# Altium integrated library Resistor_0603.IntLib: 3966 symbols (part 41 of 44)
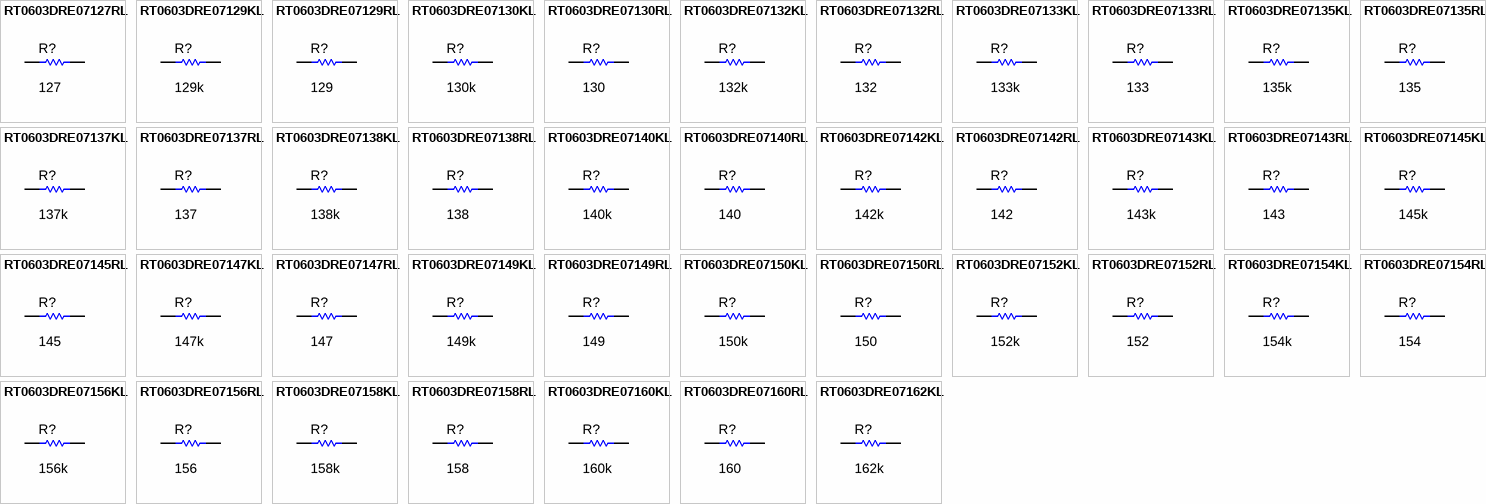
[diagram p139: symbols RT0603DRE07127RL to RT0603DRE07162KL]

## RT0603DRE07138KL
designator R?  ValueDisplayed: 138k  (hidden comment: RT0603DRE07138KL)
RES, 138 k, 0.5%, 0.1 W, 0603; Manufacturer: Yageo America; CompType: Resistor; Value: 138k; Res_ohm: 138000; Tolerance_%: 0.5; Power_W: 0.1; Value2: 0.1W; VDC_V: 75; TempCo: 50 ppm/C; SizeArea_mm2: 1.28; SizeX_mm: 1.6; SizeY_mm: 0.8; SizeZ_mm: 1; EIA_Code: E192; U/M: EA; AEC Category: Q200
signal-integrity model Resistor
simulation model Resistor
footprint 0603
footprint 0603M
footprint 0603L
footprint 0603_HV
footprint 0603S
pins: 1, 2

## RT0603DRE07138RL
designator R?  ValueDisplayed: 138  (hidden comment: RT0603DRE07138RL)
RES, 138, 0.5%, 0.1 W, 0603; Manufacturer: Yageo America; CompType: Resistor; Value: 138; Value_Code: 138R; Tolerance_%: 0.5; Power_W: 0.1; Value2: 0.1W; VDC_V: 75; TempCo: 50 ppm/C; SizeArea_mm2: 1.28; SizeX_mm: 1.6; SizeY_mm: 0.8; SizeZ_mm: 1; EIA_Code: E192; U/M: EA; AEC Category: Q200
signal-integrity model Resistor
simulation model Resistor
footprint 0603
footprint 0603M
footprint 0603L
footprint 0603_HV
footprint 0603S
pins: 1, 2

## RT0603DRE07140KL
designator R?  ValueDisplayed: 140k  (hidden comment: RT0603DRE07140KL)
RES, 140 k, 0.5%, 0.1 W, 0603; Manufacturer: Yageo America; CompType: Resistor; Value: 140k; Res_ohm: 140000; Tolerance_%: 0.5; Power_W: 0.1; Value2: 0.1W; VDC_V: 75; TempCo: 50 ppm/C; SizeArea_mm2: 1.28; SizeX_mm: 1.6; SizeY_mm: 0.8; SizeZ_mm: 1; EIA_Code: E192; U/M: EA; AEC Category: Q200
signal-integrity model Resistor
simulation model Resistor
footprint 0603
footprint 0603M
footprint 0603L
footprint 0603_HV
footprint 0603S
pins: 1, 2

## RT0603DRE07140RL
designator R?  ValueDisplayed: 140  (hidden comment: RT0603DRE07140RL)
RES, 140, 0.5%, 0.1 W, 0603; Manufacturer: Yageo America; CompType: Resistor; Value: 140; Value_Code: 140R; Tolerance_%: 0.5; Power_W: 0.1; Value2: 0.1W; VDC_V: 75; TempCo: 50 ppm/C; SizeArea_mm2: 1.28; SizeX_mm: 1.6; SizeY_mm: 0.8; SizeZ_mm: 1; EIA_Code: E192; U/M: EA; AEC Category: Q200
signal-integrity model Resistor
simulation model Resistor
footprint 0603
footprint 0603M
footprint 0603L
footprint 0603_HV
footprint 0603S
pins: 1, 2

## RT0603DRE07142KL
designator R?  ValueDisplayed: 142k  (hidden comment: RT0603DRE07142KL)
RES, 142 k, 0.5%, 0.1 W, 0603; Manufacturer: Yageo America; CompType: Resistor; Value: 142k; Res_ohm: 142000; Tolerance_%: 0.5; Power_W: 0.1; Value2: 0.1W; VDC_V: 75; TempCo: 50 ppm/C; SizeArea_mm2: 1.28; SizeX_mm: 1.6; SizeY_mm: 0.8; SizeZ_mm: 1; EIA_Code: E192; U/M: EA; AEC Category: Q200
signal-integrity model Resistor
simulation model Resistor
footprint 0603
footprint 0603M
footprint 0603L
footprint 0603_HV
footprint 0603S
pins: 1, 2

## RT0603DRE07142RL
designator R?  ValueDisplayed: 142  (hidden comment: RT0603DRE07142RL)
RES, 142, 0.5%, 0.1 W, 0603; Manufacturer: Yageo America; CompType: Resistor; Value: 142; Value_Code: 142R; Tolerance_%: 0.5; Power_W: 0.1; Value2: 0.1W; VDC_V: 75; TempCo: 50 ppm/C; SizeArea_mm2: 1.28; SizeX_mm: 1.6; SizeY_mm: 0.8; SizeZ_mm: 1; EIA_Code: E192; U/M: EA; AEC Category: Q200
signal-integrity model Resistor
simulation model Resistor
footprint 0603
footprint 0603M
footprint 0603L
footprint 0603_HV
footprint 0603S
pins: 1, 2

## RT0603DRE07143KL
designator R?  ValueDisplayed: 143k  (hidden comment: RT0603DRE07143KL)
RES, 143 k, 0.5%, 0.1 W, 0603; Manufacturer: Yageo America; CompType: Resistor; Value: 143k; Res_ohm: 143000; Tolerance_%: 0.5; Power_W: 0.1; Value2: 0.1W; VDC_V: 75; TempCo: 50 ppm/C; SizeArea_mm2: 1.28; SizeX_mm: 1.6; SizeY_mm: 0.8; SizeZ_mm: 1; EIA_Code: E192; U/M: EA; AEC Category: Q200
signal-integrity model Resistor
simulation model Resistor
footprint 0603
footprint 0603M
footprint 0603L
footprint 0603_HV
footprint 0603S
pins: 1, 2

## RT0603DRE07143RL
designator R?  ValueDisplayed: 143  (hidden comment: RT0603DRE07143RL)
RES, 143, 0.5%, 0.1 W, 0603; Manufacturer: Yageo America; CompType: Resistor; Value: 143; Value_Code: 143R; Tolerance_%: 0.5; Power_W: 0.1; Value2: 0.1W; VDC_V: 75; TempCo: 50 ppm/C; SizeArea_mm2: 1.28; SizeX_mm: 1.6; SizeY_mm: 0.8; SizeZ_mm: 1; EIA_Code: E192; U/M: EA; AEC Category: Q200
signal-integrity model Resistor
simulation model Resistor
footprint 0603
footprint 0603M
footprint 0603L
footprint 0603_HV
footprint 0603S
pins: 1, 2

## RT0603DRE07145KL
designator R?  ValueDisplayed: 145k  (hidden comment: RT0603DRE07145KL)
RES, 145 k, 0.5%, 0.1 W, 0603; Manufacturer: Yageo America; CompType: Resistor; Value: 145k; Res_ohm: 145000; Tolerance_%: 0.5; Power_W: 0.1; Value2: 0.1W; VDC_V: 75; TempCo: 50 ppm/C; SizeArea_mm2: 1.28; SizeX_mm: 1.6; SizeY_mm: 0.8; SizeZ_mm: 1; EIA_Code: E192; U/M: EA; AEC Category: Q200
signal-integrity model Resistor
simulation model Resistor
footprint 0603
footprint 0603M
footprint 0603L
footprint 0603_HV
footprint 0603S
pins: 1, 2

## RT0603DRE07145RL
designator R?  ValueDisplayed: 145  (hidden comment: RT0603DRE07145RL)
RES, 145, 0.5%, 0.1 W, 0603; Manufacturer: Yageo America; CompType: Resistor; Value: 145; Value_Code: 145R; Tolerance_%: 0.5; Power_W: 0.1; Value2: 0.1W; VDC_V: 75; TempCo: 50 ppm/C; SizeArea_mm2: 1.28; SizeX_mm: 1.6; SizeY_mm: 0.8; SizeZ_mm: 1; EIA_Code: E192; U/M: EA; AEC Category: Q200
signal-integrity model Resistor
simulation model Resistor
footprint 0603
footprint 0603M
footprint 0603L
footprint 0603_HV
footprint 0603S
pins: 1, 2

## RT0603DRE07147KL
designator R?  ValueDisplayed: 147k  (hidden comment: RT0603DRE07147KL)
RES, 147 k, 0.5%, 0.1 W, 0603; Manufacturer: Yageo America; CompType: Resistor; Value: 147k; Res_ohm: 147000; Tolerance_%: 0.5; Power_W: 0.1; Value2: 0.1W; VDC_V: 75; TempCo: 50 ppm/C; SizeArea_mm2: 1.28; SizeX_mm: 1.6; SizeY_mm: 0.8; SizeZ_mm: 1; EIA_Code: E192; U/M: EA; AEC Category: Q200
signal-integrity model Resistor
simulation model Resistor
footprint 0603
footprint 0603M
footprint 0603L
footprint 0603_HV
footprint 0603S
pins: 1, 2

## RT0603DRE07147RL
designator R?  ValueDisplayed: 147  (hidden comment: RT0603DRE07147RL)
RES, 147, 0.5%, 0.1 W, 0603; Manufacturer: Yageo America; CompType: Resistor; Value: 147; Value_Code: 147R; Tolerance_%: 0.5; Power_W: 0.1; Value2: 0.1W; VDC_V: 75; TempCo: 50 ppm/C; SizeArea_mm2: 1.28; SizeX_mm: 1.6; SizeY_mm: 0.8; SizeZ_mm: 1; EIA_Code: E192; U/M: EA; AEC Category: Q200
signal-integrity model Resistor
simulation model Resistor
footprint 0603
footprint 0603M
footprint 0603L
footprint 0603_HV
footprint 0603S
pins: 1, 2

## RT0603DRE07149KL
designator R?  ValueDisplayed: 149k  (hidden comment: RT0603DRE07149KL)
RES, 149 k, 0.5%, 0.1 W, 0603; Manufacturer: Yageo America; CompType: Resistor; Value: 149k; Res_ohm: 149000; Tolerance_%: 0.5; Power_W: 0.1; Value2: 0.1W; VDC_V: 75; TempCo: 50 ppm/C; SizeArea_mm2: 1.28; SizeX_mm: 1.6; SizeY_mm: 0.8; SizeZ_mm: 1; EIA_Code: E192; U/M: EA; AEC Category: Q200
signal-integrity model Resistor
simulation model Resistor
footprint 0603
footprint 0603M
footprint 0603L
footprint 0603_HV
footprint 0603S
pins: 1, 2

## RT0603DRE07149RL
designator R?  ValueDisplayed: 149  (hidden comment: RT0603DRE07149RL)
RES, 149, 0.5%, 0.1 W, 0603; Manufacturer: Yageo America; CompType: Resistor; Value: 149; Value_Code: 149R; Tolerance_%: 0.5; Power_W: 0.1; Value2: 0.1W; VDC_V: 75; TempCo: 50 ppm/C; SizeArea_mm2: 1.28; SizeX_mm: 1.6; SizeY_mm: 0.8; SizeZ_mm: 1; EIA_Code: E192; U/M: EA; AEC Category: Q200
signal-integrity model Resistor
simulation model Resistor
footprint 0603
footprint 0603M
footprint 0603L
footprint 0603_HV
footprint 0603S
pins: 1, 2

## RT0603DRE07150KL
designator R?  ValueDisplayed: 150k  (hidden comment: RT0603DRE07150KL)
RES, 150 k, 0.5%, 0.1 W, 0603; Manufacturer: Yageo America; CompType: Resistor; Value: 150k; Res_ohm: 150000; Tolerance_%: 0.5; Power_W: 0.1; Value2: 0.1W; VDC_V: 75; TempCo: 50 ppm/C; SizeArea_mm2: 1.28; SizeX_mm: 1.6; SizeY_mm: 0.8; SizeZ_mm: 1; EIA_Code: E192; U/M: EA; AEC Category: Q200
signal-integrity model Resistor
simulation model Resistor
footprint 0603
footprint 0603M
footprint 0603L
footprint 0603_HV
footprint 0603S
pins: 1, 2

## RT0603DRE07150RL
designator R?  ValueDisplayed: 150  (hidden comment: RT0603DRE07150RL)
RES, 150, 0.5%, 0.1 W, 0603; Manufacturer: Yageo America; CompType: Resistor; Value: 150; Value_Code: 150R; Tolerance_%: 0.5; Power_W: 0.1; Value2: 0.1W; VDC_V: 75; TempCo: 50 ppm/C; SizeArea_mm2: 1.28; SizeX_mm: 1.6; SizeY_mm: 0.8; SizeZ_mm: 1; EIA_Code: E192; U/M: EA; AEC Category: Q200
signal-integrity model Resistor
simulation model Resistor
footprint 0603
footprint 0603M
footprint 0603L
footprint 0603_HV
footprint 0603S
pins: 1, 2

## RT0603DRE07152KL
designator R?  ValueDisplayed: 152k  (hidden comment: RT0603DRE07152KL)
RES, 152 k, 0.5%, 0.1 W, 0603; Manufacturer: Yageo America; CompType: Resistor; Value: 152k; Res_ohm: 152000; Tolerance_%: 0.5; Power_W: 0.1; Value2: 0.1W; VDC_V: 75; TempCo: 50 ppm/C; SizeArea_mm2: 1.28; SizeX_mm: 1.6; SizeY_mm: 0.8; SizeZ_mm: 1; EIA_Code: E192; U/M: EA; AEC Category: Q200
signal-integrity model Resistor
simulation model Resistor
footprint 0603
footprint 0603M
footprint 0603L
footprint 0603_HV
footprint 0603S
pins: 1, 2

## RT0603DRE07152RL
designator R?  ValueDisplayed: 152  (hidden comment: RT0603DRE07152RL)
RES, 152, 0.5%, 0.1 W, 0603; Manufacturer: Yageo America; CompType: Resistor; Value: 152; Value_Code: 152R; Tolerance_%: 0.5; Power_W: 0.1; Value2: 0.1W; VDC_V: 75; TempCo: 50 ppm/C; SizeArea_mm2: 1.28; SizeX_mm: 1.6; SizeY_mm: 0.8; SizeZ_mm: 1; EIA_Code: E192; U/M: EA; AEC Category: Q200
signal-integrity model Resistor
simulation model Resistor
footprint 0603
footprint 0603M
footprint 0603L
footprint 0603_HV
footprint 0603S
pins: 1, 2

## RT0603DRE07154KL
designator R?  ValueDisplayed: 154k  (hidden comment: RT0603DRE07154KL)
RES, 154 k, 0.5%, 0.1 W, 0603; Manufacturer: Yageo America; CompType: Resistor; Value: 154k; Res_ohm: 154000; Tolerance_%: 0.5; Power_W: 0.1; Value2: 0.1W; VDC_V: 75; TempCo: 50 ppm/C; SizeArea_mm2: 1.28; SizeX_mm: 1.6; SizeY_mm: 0.8; SizeZ_mm: 1; EIA_Code: E192; U/M: EA; AEC Category: Q200
signal-integrity model Resistor
simulation model Resistor
footprint 0603
footprint 0603M
footprint 0603L
footprint 0603_HV
footprint 0603S
pins: 1, 2

## RT0603DRE07154RL
designator R?  ValueDisplayed: 154  (hidden comment: RT0603DRE07154RL)
RES, 154, 0.5%, 0.1 W, 0603; Manufacturer: Yageo America; CompType: Resistor; Value: 154; Value_Code: 154R; Tolerance_%: 0.5; Power_W: 0.1; Value2: 0.1W; VDC_V: 75; TempCo: 50 ppm/C; SizeArea_mm2: 1.28; SizeX_mm: 1.6; SizeY_mm: 0.8; SizeZ_mm: 1; EIA_Code: E192; U/M: EA; AEC Category: Q200
signal-integrity model Resistor
simulation model Resistor
footprint 0603
footprint 0603M
footprint 0603L
footprint 0603_HV
footprint 0603S
pins: 1, 2

## RT0603DRE07156KL
designator R?  ValueDisplayed: 156k  (hidden comment: RT0603DRE07156KL)
RES, 156 k, 0.5%, 0.1 W, 0603; Manufacturer: Yageo America; CompType: Resistor; Value: 156k; Res_ohm: 156000; Tolerance_%: 0.5; Power_W: 0.1; Value2: 0.1W; VDC_V: 75; TempCo: 50 ppm/C; SizeArea_mm2: 1.28; SizeX_mm: 1.6; SizeY_mm: 0.8; SizeZ_mm: 1; EIA_Code: E192; U/M: EA; AEC Category: Q200
signal-integrity model Resistor
simulation model Resistor
footprint 0603
footprint 0603M
footprint 0603L
footprint 0603_HV
footprint 0603S
pins: 1, 2

## RT0603DRE07156RL
designator R?  ValueDisplayed: 156  (hidden comment: RT0603DRE07156RL)
RES, 156, 0.5%, 0.1 W, 0603; Manufacturer: Yageo America; CompType: Resistor; Value: 156; Value_Code: 156R; Tolerance_%: 0.5; Power_W: 0.1; Value2: 0.1W; VDC_V: 75; TempCo: 50 ppm/C; SizeArea_mm2: 1.28; SizeX_mm: 1.6; SizeY_mm: 0.8; SizeZ_mm: 1; EIA_Code: E192; U/M: EA; AEC Category: Q200
signal-integrity model Resistor
simulation model Resistor
footprint 0603
footprint 0603M
footprint 0603L
footprint 0603_HV
footprint 0603S
pins: 1, 2

## RT0603DRE07158KL
designator R?  ValueDisplayed: 158k  (hidden comment: RT0603DRE07158KL)
RES, 158 k, 0.5%, 0.1 W, 0603; Manufacturer: Yageo America; CompType: Resistor; Value: 158k; Res_ohm: 158000; Tolerance_%: 0.5; Power_W: 0.1; Value2: 0.1W; VDC_V: 75; TempCo: 50 ppm/C; SizeArea_mm2: 1.28; SizeX_mm: 1.6; SizeY_mm: 0.8; SizeZ_mm: 1; EIA_Code: E192; U/M: EA; AEC Category: Q200
signal-integrity model Resistor
simulation model Resistor
footprint 0603
footprint 0603M
footprint 0603L
footprint 0603_HV
footprint 0603S
pins: 1, 2

## RT0603DRE07158RL
designator R?  ValueDisplayed: 158  (hidden comment: RT0603DRE07158RL)
RES, 158, 0.5%, 0.1 W, 0603; Manufacturer: Yageo America; CompType: Resistor; Value: 158; Value_Code: 158R; Tolerance_%: 0.5; Power_W: 0.1; Value2: 0.1W; VDC_V: 75; TempCo: 50 ppm/C; SizeArea_mm2: 1.28; SizeX_mm: 1.6; SizeY_mm: 0.8; SizeZ_mm: 1; EIA_Code: E192; U/M: EA; AEC Category: Q200
signal-integrity model Resistor
simulation model Resistor
footprint 0603
footprint 0603M
footprint 0603L
footprint 0603_HV
footprint 0603S
pins: 1, 2

## RT0603DRE07160KL
designator R?  ValueDisplayed: 160k  (hidden comment: RT0603DRE07160KL)
RES, 160 k, 0.5%, 0.1 W, 0603; Manufacturer: Yageo America; CompType: Resistor; Value: 160k; Res_ohm: 160000; Tolerance_%: 0.5; Power_W: 0.1; Value2: 0.1W; VDC_V: 75; TempCo: 50 ppm/C; SizeArea_mm2: 1.28; SizeX_mm: 1.6; SizeY_mm: 0.8; SizeZ_mm: 1; EIA_Code: E192; U/M: EA; AEC Category: Q200
signal-integrity model Resistor
simulation model Resistor
footprint 0603
footprint 0603M
footprint 0603L
footprint 0603_HV
footprint 0603S
pins: 1, 2

## RT0603DRE07160RL
designator R?  ValueDisplayed: 160  (hidden comment: RT0603DRE07160RL)
RES, 160, 0.5%, 0.1 W, 0603; Manufacturer: Yageo America; CompType: Resistor; Value: 160; Value_Code: 160R; Tolerance_%: 0.5; Power_W: 0.1; Value2: 0.1W; VDC_V: 75; TempCo: 50 ppm/C; SizeArea_mm2: 1.28; SizeX_mm: 1.6; SizeY_mm: 0.8; SizeZ_mm: 1; EIA_Code: E192; U/M: EA; AEC Category: Q200
signal-integrity model Resistor
simulation model Resistor
footprint 0603
footprint 0603M
footprint 0603L
footprint 0603_HV
footprint 0603S
pins: 1, 2

## RT0603DRE07162KL
designator R?  ValueDisplayed: 162k  (hidden comment: RT0603DRE07162KL)
RES, 162 k, 0.5%, 0.1 W, 0603; Manufacturer: Yageo America; CompType: Resistor; Value: 162k; Res_ohm: 162000; Tolerance_%: 0.5; Power_W: 0.1; Value2: 0.1W; VDC_V: 75; TempCo: 50 ppm/C; SizeArea_mm2: 1.28; SizeX_mm: 1.6; SizeY_mm: 0.8; SizeZ_mm: 1; EIA_Code: E192; U/M: EA; AEC Category: Q200
signal-integrity model Resistor
simulation model Resistor
footprint 0603
footprint 0603M
footprint 0603L
footprint 0603_HV
footprint 0603S
pins: 1, 2

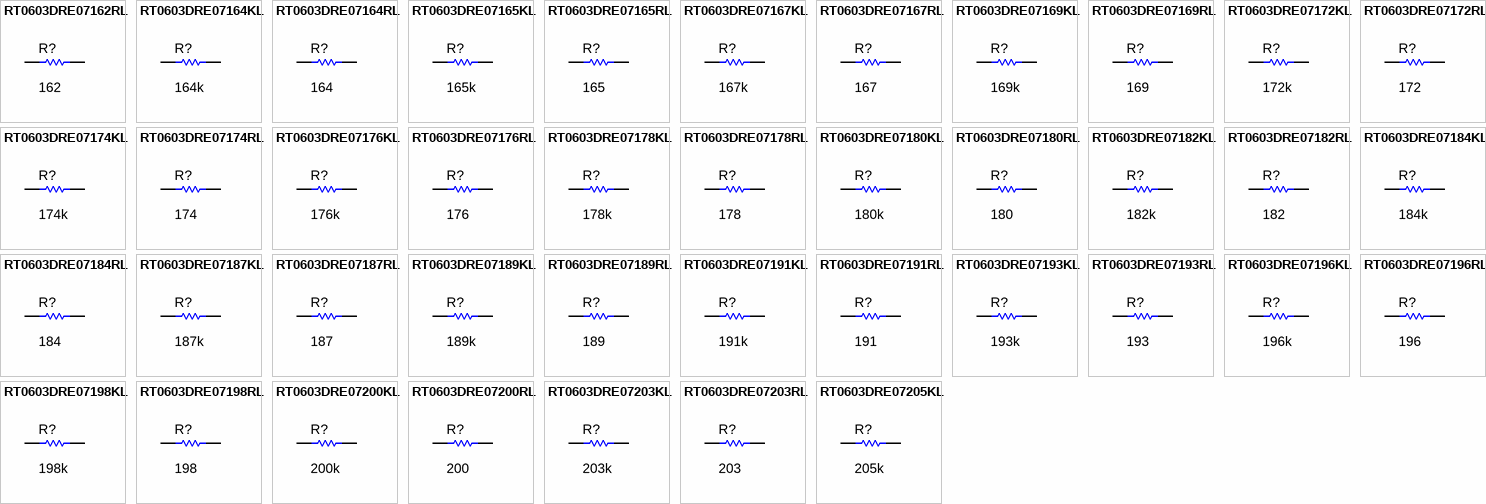
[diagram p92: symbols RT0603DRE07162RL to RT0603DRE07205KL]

## RT0603DRE07162RL
designator R?  ValueDisplayed: 162  (hidden comment: RT0603DRE07162RL)
RES, 162, 0.5%, 0.1 W, 0603; Manufacturer: Yageo America; CompType: Resistor; Value: 162; Value_Code: 162R; Tolerance_%: 0.5; Power_W: 0.1; Value2: 0.1W; VDC_V: 75; TempCo: 50 ppm/C; SizeArea_mm2: 1.28; SizeX_mm: 1.6; SizeY_mm: 0.8; SizeZ_mm: 1; EIA_Code: E192; U/M: EA; AEC Category: Q200
signal-integrity model Resistor
simulation model Resistor
footprint 0603
footprint 0603M
footprint 0603L
footprint 0603_HV
footprint 0603S
pins: 1, 2

## RT0603DRE07164KL
designator R?  ValueDisplayed: 164k  (hidden comment: RT0603DRE07164KL)
RES, 164 k, 0.5%, 0.1 W, 0603; Manufacturer: Yageo America; CompType: Resistor; Value: 164k; Res_ohm: 164000; Tolerance_%: 0.5; Power_W: 0.1; Value2: 0.1W; VDC_V: 75; TempCo: 50 ppm/C; SizeArea_mm2: 1.28; SizeX_mm: 1.6; SizeY_mm: 0.8; SizeZ_mm: 1; EIA_Code: E192; U/M: EA; AEC Category: Q200
signal-integrity model Resistor
simulation model Resistor
footprint 0603
footprint 0603M
footprint 0603L
footprint 0603_HV
footprint 0603S
pins: 1, 2

## RT0603DRE07164RL
designator R?  ValueDisplayed: 164  (hidden comment: RT0603DRE07164RL)
RES, 164, 0.5%, 0.1 W, 0603; Manufacturer: Yageo America; CompType: Resistor; Value: 164; Value_Code: 164R; Tolerance_%: 0.5; Power_W: 0.1; Value2: 0.1W; VDC_V: 75; TempCo: 50 ppm/C; SizeArea_mm2: 1.28; SizeX_mm: 1.6; SizeY_mm: 0.8; SizeZ_mm: 1; EIA_Code: E192; U/M: EA; AEC Category: Q200
signal-integrity model Resistor
simulation model Resistor
footprint 0603
footprint 0603M
footprint 0603L
footprint 0603_HV
footprint 0603S
pins: 1, 2

## RT0603DRE07165KL
designator R?  ValueDisplayed: 165k  (hidden comment: RT0603DRE07165KL)
RES, 165 k, 0.5%, 0.1 W, 0603; Manufacturer: Yageo America; CompType: Resistor; Value: 165k; Res_ohm: 165000; Tolerance_%: 0.5; Power_W: 0.1; Value2: 0.1W; VDC_V: 75; TempCo: 50 ppm/C; SizeArea_mm2: 1.28; SizeX_mm: 1.6; SizeY_mm: 0.8; SizeZ_mm: 1; EIA_Code: E192; U/M: EA; AEC Category: Q200
signal-integrity model Resistor
simulation model Resistor
footprint 0603
footprint 0603M
footprint 0603L
footprint 0603_HV
footprint 0603S
pins: 1, 2

## RT0603DRE07165RL
designator R?  ValueDisplayed: 165  (hidden comment: RT0603DRE07165RL)
RES, 165, 0.5%, 0.1 W, 0603; Manufacturer: Yageo America; CompType: Resistor; Value: 165; Value_Code: 165R; Tolerance_%: 0.5; Power_W: 0.1; Value2: 0.1W; VDC_V: 75; TempCo: 50 ppm/C; SizeArea_mm2: 1.28; SizeX_mm: 1.6; SizeY_mm: 0.8; SizeZ_mm: 1; EIA_Code: E192; U/M: EA; AEC Category: Q200
signal-integrity model Resistor
simulation model Resistor
footprint 0603
footprint 0603M
footprint 0603L
footprint 0603_HV
footprint 0603S
pins: 1, 2

## RT0603DRE07167KL
designator R?  ValueDisplayed: 167k  (hidden comment: RT0603DRE07167KL)
RES, 167 k, 0.5%, 0.1 W, 0603; Manufacturer: Yageo America; CompType: Resistor; Value: 167k; Res_ohm: 167000; Tolerance_%: 0.5; Power_W: 0.1; Value2: 0.1W; VDC_V: 75; TempCo: 50 ppm/C; SizeArea_mm2: 1.28; SizeX_mm: 1.6; SizeY_mm: 0.8; SizeZ_mm: 1; EIA_Code: E192; U/M: EA; AEC Category: Q200
signal-integrity model Resistor
simulation model Resistor
footprint 0603
footprint 0603M
footprint 0603L
footprint 0603_HV
footprint 0603S
pins: 1, 2

## RT0603DRE07167RL
designator R?  ValueDisplayed: 167  (hidden comment: RT0603DRE07167RL)
RES, 167, 0.5%, 0.1 W, 0603; Manufacturer: Yageo America; CompType: Resistor; Value: 167; Value_Code: 167R; Tolerance_%: 0.5; Power_W: 0.1; Value2: 0.1W; VDC_V: 75; TempCo: 50 ppm/C; SizeArea_mm2: 1.28; SizeX_mm: 1.6; SizeY_mm: 0.8; SizeZ_mm: 1; EIA_Code: E192; U/M: EA; AEC Category: Q200
signal-integrity model Resistor
simulation model Resistor
footprint 0603
footprint 0603M
footprint 0603L
footprint 0603_HV
footprint 0603S
pins: 1, 2

## RT0603DRE07169KL
designator R?  ValueDisplayed: 169k  (hidden comment: RT0603DRE07169KL)
RES, 169 k, 0.5%, 0.1 W, 0603; Manufacturer: Yageo America; CompType: Resistor; Value: 169k; Res_ohm: 169000; Tolerance_%: 0.5; Power_W: 0.1; Value2: 0.1W; VDC_V: 75; TempCo: 50 ppm/C; SizeArea_mm2: 1.28; SizeX_mm: 1.6; SizeY_mm: 0.8; SizeZ_mm: 1; EIA_Code: E192; U/M: EA; AEC Category: Q200
signal-integrity model Resistor
simulation model Resistor
footprint 0603
footprint 0603M
footprint 0603L
footprint 0603_HV
footprint 0603S
pins: 1, 2

## RT0603DRE07169RL
designator R?  ValueDisplayed: 169  (hidden comment: RT0603DRE07169RL)
RES, 169, 0.5%, 0.1 W, 0603; Manufacturer: Yageo America; CompType: Resistor; Value: 169; Value_Code: 169R; Tolerance_%: 0.5; Power_W: 0.1; Value2: 0.1W; VDC_V: 75; TempCo: 50 ppm/C; SizeArea_mm2: 1.28; SizeX_mm: 1.6; SizeY_mm: 0.8; SizeZ_mm: 1; EIA_Code: E192; U/M: EA; AEC Category: Q200
signal-integrity model Resistor
simulation model Resistor
footprint 0603
footprint 0603M
footprint 0603L
footprint 0603_HV
footprint 0603S
pins: 1, 2

## RT0603DRE07172KL
designator R?  ValueDisplayed: 172k  (hidden comment: RT0603DRE07172KL)
RES, 172 k, 0.5%, 0.1 W, 0603; Manufacturer: Yageo America; CompType: Resistor; Value: 172k; Res_ohm: 172000; Tolerance_%: 0.5; Power_W: 0.1; Value2: 0.1W; VDC_V: 75; TempCo: 50 ppm/C; SizeArea_mm2: 1.28; SizeX_mm: 1.6; SizeY_mm: 0.8; SizeZ_mm: 1; EIA_Code: E192; U/M: EA; AEC Category: Q200
signal-integrity model Resistor
simulation model Resistor
footprint 0603
footprint 0603M
footprint 0603L
footprint 0603_HV
footprint 0603S
pins: 1, 2

## RT0603DRE07172RL
designator R?  ValueDisplayed: 172  (hidden comment: RT0603DRE07172RL)
RES, 172, 0.5%, 0.1 W, 0603; Manufacturer: Yageo America; CompType: Resistor; Value: 172; Value_Code: 172R; Tolerance_%: 0.5; Power_W: 0.1; Value2: 0.1W; VDC_V: 75; TempCo: 50 ppm/C; SizeArea_mm2: 1.28; SizeX_mm: 1.6; SizeY_mm: 0.8; SizeZ_mm: 1; EIA_Code: E192; U/M: EA; AEC Category: Q200
signal-integrity model Resistor
simulation model Resistor
footprint 0603
footprint 0603M
footprint 0603L
footprint 0603_HV
footprint 0603S
pins: 1, 2

## RT0603DRE07174KL
designator R?  ValueDisplayed: 174k  (hidden comment: RT0603DRE07174KL)
RES, 174 k, 0.5%, 0.1 W, 0603; Manufacturer: Yageo America; CompType: Resistor; Value: 174k; Res_ohm: 174000; Tolerance_%: 0.5; Power_W: 0.1; Value2: 0.1W; VDC_V: 75; TempCo: 50 ppm/C; SizeArea_mm2: 1.28; SizeX_mm: 1.6; SizeY_mm: 0.8; SizeZ_mm: 1; EIA_Code: E192; U/M: EA; AEC Category: Q200
signal-integrity model Resistor
simulation model Resistor
footprint 0603
footprint 0603M
footprint 0603L
footprint 0603_HV
footprint 0603S
pins: 1, 2

## RT0603DRE07174RL
designator R?  ValueDisplayed: 174  (hidden comment: RT0603DRE07174RL)
RES, 174, 0.5%, 0.1 W, 0603; Manufacturer: Yageo America; CompType: Resistor; Value: 174; Value_Code: 174R; Tolerance_%: 0.5; Power_W: 0.1; Value2: 0.1W; VDC_V: 75; TempCo: 50 ppm/C; SizeArea_mm2: 1.28; SizeX_mm: 1.6; SizeY_mm: 0.8; SizeZ_mm: 1; EIA_Code: E192; U/M: EA; AEC Category: Q200
signal-integrity model Resistor
simulation model Resistor
footprint 0603
footprint 0603M
footprint 0603L
footprint 0603_HV
footprint 0603S
pins: 1, 2

## RT0603DRE07176KL
designator R?  ValueDisplayed: 176k  (hidden comment: RT0603DRE07176KL)
RES, 176 k, 0.5%, 0.1 W, 0603; Manufacturer: Yageo America; CompType: Resistor; Value: 176k; Res_ohm: 176000; Tolerance_%: 0.5; Power_W: 0.1; Value2: 0.1W; VDC_V: 75; TempCo: 50 ppm/C; SizeArea_mm2: 1.28; SizeX_mm: 1.6; SizeY_mm: 0.8; SizeZ_mm: 1; EIA_Code: E192; U/M: EA; AEC Category: Q200
signal-integrity model Resistor
simulation model Resistor
footprint 0603
footprint 0603M
footprint 0603L
footprint 0603_HV
footprint 0603S
pins: 1, 2

## RT0603DRE07176RL
designator R?  ValueDisplayed: 176  (hidden comment: RT0603DRE07176RL)
RES, 176, 0.5%, 0.1 W, 0603; Manufacturer: Yageo America; CompType: Resistor; Value: 176; Value_Code: 176R; Tolerance_%: 0.5; Power_W: 0.1; Value2: 0.1W; VDC_V: 75; TempCo: 50 ppm/C; SizeArea_mm2: 1.28; SizeX_mm: 1.6; SizeY_mm: 0.8; SizeZ_mm: 1; EIA_Code: E192; U/M: EA; AEC Category: Q200
signal-integrity model Resistor
simulation model Resistor
footprint 0603
footprint 0603M
footprint 0603L
footprint 0603_HV
footprint 0603S
pins: 1, 2

## RT0603DRE07178KL
designator R?  ValueDisplayed: 178k  (hidden comment: RT0603DRE07178KL)
RES, 178 k, 0.5%, 0.1 W, 0603; Manufacturer: Yageo America; CompType: Resistor; Value: 178k; Res_ohm: 178000; Tolerance_%: 0.5; Power_W: 0.1; Value2: 0.1W; VDC_V: 75; TempCo: 50 ppm/C; SizeArea_mm2: 1.28; SizeX_mm: 1.6; SizeY_mm: 0.8; SizeZ_mm: 1; EIA_Code: E192; U/M: EA; AEC Category: Q200
signal-integrity model Resistor
simulation model Resistor
footprint 0603
footprint 0603M
footprint 0603L
footprint 0603_HV
footprint 0603S
pins: 1, 2

## RT0603DRE07178RL
designator R?  ValueDisplayed: 178  (hidden comment: RT0603DRE07178RL)
RES, 178, 0.5%, 0.1 W, 0603; Manufacturer: Yageo America; CompType: Resistor; Value: 178; Value_Code: 178R; Tolerance_%: 0.5; Power_W: 0.1; Value2: 0.1W; VDC_V: 75; TempCo: 50 ppm/C; SizeArea_mm2: 1.28; SizeX_mm: 1.6; SizeY_mm: 0.8; SizeZ_mm: 1; EIA_Code: E192; U/M: EA; AEC Category: Q200
signal-integrity model Resistor
simulation model Resistor
footprint 0603
footprint 0603M
footprint 0603L
footprint 0603_HV
footprint 0603S
pins: 1, 2

## RT0603DRE07180KL
designator R?  ValueDisplayed: 180k  (hidden comment: RT0603DRE07180KL)
RES, 180 k, 0.5%, 0.1 W, 0603; Manufacturer: Yageo America; CompType: Resistor; Value: 180k; Res_ohm: 180000; Tolerance_%: 0.5; Power_W: 0.1; Value2: 0.1W; VDC_V: 75; TempCo: 50 ppm/C; SizeArea_mm2: 1.28; SizeX_mm: 1.6; SizeY_mm: 0.8; SizeZ_mm: 1; EIA_Code: E192; U/M: EA; AEC Category: Q200
signal-integrity model Resistor
simulation model Resistor
footprint 0603
footprint 0603M
footprint 0603L
footprint 0603_HV
footprint 0603S
pins: 1, 2

## RT0603DRE07180RL
designator R?  ValueDisplayed: 180  (hidden comment: RT0603DRE07180RL)
RES, 180, 0.5%, 0.1 W, 0603; Manufacturer: Yageo America; CompType: Resistor; Value: 180; Value_Code: 180R; Tolerance_%: 0.5; Power_W: 0.1; Value2: 0.1W; VDC_V: 75; TempCo: 50 ppm/C; SizeArea_mm2: 1.28; SizeX_mm: 1.6; SizeY_mm: 0.8; SizeZ_mm: 1; EIA_Code: E192; U/M: EA; AEC Category: Q200
signal-integrity model Resistor
simulation model Resistor
footprint 0603
footprint 0603M
footprint 0603L
footprint 0603_HV
footprint 0603S
pins: 1, 2

## RT0603DRE07182KL
designator R?  ValueDisplayed: 182k  (hidden comment: RT0603DRE07182KL)
RES, 182 k, 0.5%, 0.1 W, 0603; Manufacturer: Yageo America; CompType: Resistor; Value: 182k; Res_ohm: 182000; Tolerance_%: 0.5; Power_W: 0.1; Value2: 0.1W; VDC_V: 75; TempCo: 50 ppm/C; SizeArea_mm2: 1.28; SizeX_mm: 1.6; SizeY_mm: 0.8; SizeZ_mm: 1; EIA_Code: E192; U/M: EA; AEC Category: Q200
signal-integrity model Resistor
simulation model Resistor
footprint 0603
footprint 0603M
footprint 0603L
footprint 0603_HV
footprint 0603S
pins: 1, 2

## RT0603DRE07182RL
designator R?  ValueDisplayed: 182  (hidden comment: RT0603DRE07182RL)
RES, 182, 0.5%, 0.1 W, 0603; Manufacturer: Yageo America; CompType: Resistor; Value: 182; Value_Code: 182R; Tolerance_%: 0.5; Power_W: 0.1; Value2: 0.1W; VDC_V: 75; TempCo: 50 ppm/C; SizeArea_mm2: 1.28; SizeX_mm: 1.6; SizeY_mm: 0.8; SizeZ_mm: 1; EIA_Code: E192; U/M: EA; AEC Category: Q200
signal-integrity model Resistor
simulation model Resistor
footprint 0603
footprint 0603M
footprint 0603L
footprint 0603_HV
footprint 0603S
pins: 1, 2

## RT0603DRE07184KL
designator R?  ValueDisplayed: 184k  (hidden comment: RT0603DRE07184KL)
RES, 184 k, 0.5%, 0.1 W, 0603; Manufacturer: Yageo America; CompType: Resistor; Value: 184k; Res_ohm: 184000; Tolerance_%: 0.5; Power_W: 0.1; Value2: 0.1W; VDC_V: 75; TempCo: 50 ppm/C; SizeArea_mm2: 1.28; SizeX_mm: 1.6; SizeY_mm: 0.8; SizeZ_mm: 1; EIA_Code: E192; U/M: EA; AEC Category: Q200
signal-integrity model Resistor
simulation model Resistor
footprint 0603
footprint 0603M
footprint 0603L
footprint 0603_HV
footprint 0603S
pins: 1, 2

## RT0603DRE07184RL
designator R?  ValueDisplayed: 184  (hidden comment: RT0603DRE07184RL)
RES, 184, 0.5%, 0.1 W, 0603; Manufacturer: Yageo America; CompType: Resistor; Value: 184; Value_Code: 184R; Tolerance_%: 0.5; Power_W: 0.1; Value2: 0.1W; VDC_V: 75; TempCo: 50 ppm/C; SizeArea_mm2: 1.28; SizeX_mm: 1.6; SizeY_mm: 0.8; SizeZ_mm: 1; EIA_Code: E192; U/M: EA; AEC Category: Q200
signal-integrity model Resistor
simulation model Resistor
footprint 0603
footprint 0603M
footprint 0603L
footprint 0603_HV
footprint 0603S
pins: 1, 2

## RT0603DRE07187KL
designator R?  ValueDisplayed: 187k  (hidden comment: RT0603DRE07187KL)
RES, 187 k, 0.5%, 0.1 W, 0603; Manufacturer: Yageo America; CompType: Resistor; Value: 187k; Res_ohm: 187000; Tolerance_%: 0.5; Power_W: 0.1; Value2: 0.1W; VDC_V: 75; TempCo: 50 ppm/C; SizeArea_mm2: 1.28; SizeX_mm: 1.6; SizeY_mm: 0.8; SizeZ_mm: 1; EIA_Code: E192; U/M: EA; AEC Category: Q200
signal-integrity model Resistor
simulation model Resistor
footprint 0603
footprint 0603M
footprint 0603L
footprint 0603_HV
footprint 0603S
pins: 1, 2

## RT0603DRE07187RL
designator R?  ValueDisplayed: 187  (hidden comment: RT0603DRE07187RL)
RES, 187, 0.5%, 0.1 W, 0603; Manufacturer: Yageo America; CompType: Resistor; Value: 187; Value_Code: 187R; Tolerance_%: 0.5; Power_W: 0.1; Value2: 0.1W; VDC_V: 75; TempCo: 50 ppm/C; SizeArea_mm2: 1.28; SizeX_mm: 1.6; SizeY_mm: 0.8; SizeZ_mm: 1; EIA_Code: E192; U/M: EA; AEC Category: Q200
signal-integrity model Resistor
simulation model Resistor
footprint 0603
footprint 0603M
footprint 0603L
footprint 0603_HV
footprint 0603S
pins: 1, 2

## RT0603DRE07189KL
designator R?  ValueDisplayed: 189k  (hidden comment: RT0603DRE07189KL)
RES, 189 k, 0.5%, 0.1 W, 0603; Manufacturer: Yageo America; CompType: Resistor; Value: 189k; Res_ohm: 189000; Tolerance_%: 0.5; Power_W: 0.1; Value2: 0.1W; VDC_V: 75; TempCo: 50 ppm/C; SizeArea_mm2: 1.28; SizeX_mm: 1.6; SizeY_mm: 0.8; SizeZ_mm: 1; EIA_Code: E192; U/M: EA; AEC Category: Q200
signal-integrity model Resistor
simulation model Resistor
footprint 0603
footprint 0603M
footprint 0603L
footprint 0603_HV
footprint 0603S
pins: 1, 2

## RT0603DRE07189RL
designator R?  ValueDisplayed: 189  (hidden comment: RT0603DRE07189RL)
RES, 189, 0.5%, 0.1 W, 0603; Manufacturer: Yageo America; CompType: Resistor; Value: 189; Value_Code: 189R; Tolerance_%: 0.5; Power_W: 0.1; Value2: 0.1W; VDC_V: 75; TempCo: 50 ppm/C; SizeArea_mm2: 1.28; SizeX_mm: 1.6; SizeY_mm: 0.8; SizeZ_mm: 1; EIA_Code: E192; U/M: EA; AEC Category: Q200
signal-integrity model Resistor
simulation model Resistor
footprint 0603
footprint 0603M
footprint 0603L
footprint 0603_HV
footprint 0603S
pins: 1, 2

## RT0603DRE07191KL
designator R?  ValueDisplayed: 191k  (hidden comment: RT0603DRE07191KL)
RES, 191 k, 0.5%, 0.1 W, 0603; Manufacturer: Yageo America; CompType: Resistor; Value: 191k; Res_ohm: 191000; Tolerance_%: 0.5; Power_W: 0.1; Value2: 0.1W; VDC_V: 75; TempCo: 50 ppm/C; SizeArea_mm2: 1.28; SizeX_mm: 1.6; SizeY_mm: 0.8; SizeZ_mm: 1; EIA_Code: E192; U/M: EA; AEC Category: Q200
signal-integrity model Resistor
simulation model Resistor
footprint 0603
footprint 0603M
footprint 0603L
footprint 0603_HV
footprint 0603S
pins: 1, 2

## RT0603DRE07191RL
designator R?  ValueDisplayed: 191  (hidden comment: RT0603DRE07191RL)
RES, 191, 0.5%, 0.1 W, 0603; Manufacturer: Yageo America; CompType: Resistor; Value: 191; Value_Code: 191R; Tolerance_%: 0.5; Power_W: 0.1; Value2: 0.1W; VDC_V: 75; TempCo: 50 ppm/C; SizeArea_mm2: 1.28; SizeX_mm: 1.6; SizeY_mm: 0.8; SizeZ_mm: 1; EIA_Code: E192; U/M: EA; AEC Category: Q200
signal-integrity model Resistor
simulation model Resistor
footprint 0603
footprint 0603M
footprint 0603L
footprint 0603_HV
footprint 0603S
pins: 1, 2

## RT0603DRE07193KL
designator R?  ValueDisplayed: 193k  (hidden comment: RT0603DRE07193KL)
RES, 193 k, 0.5%, 0.1 W, 0603; Manufacturer: Yageo America; CompType: Resistor; Value: 193k; Res_ohm: 193000; Tolerance_%: 0.5; Power_W: 0.1; Value2: 0.1W; VDC_V: 75; TempCo: 50 ppm/C; SizeArea_mm2: 1.28; SizeX_mm: 1.6; SizeY_mm: 0.8; SizeZ_mm: 1; EIA_Code: E192; U/M: EA; AEC Category: Q200
signal-integrity model Resistor
simulation model Resistor
footprint 0603
footprint 0603M
footprint 0603L
footprint 0603_HV
footprint 0603S
pins: 1, 2

## RT0603DRE07193RL
designator R?  ValueDisplayed: 193  (hidden comment: RT0603DRE07193RL)
RES, 193, 0.5%, 0.1 W, 0603; Manufacturer: Yageo America; CompType: Resistor; Value: 193; Value_Code: 193R; Tolerance_%: 0.5; Power_W: 0.1; Value2: 0.1W; VDC_V: 75; TempCo: 50 ppm/C; SizeArea_mm2: 1.28; SizeX_mm: 1.6; SizeY_mm: 0.8; SizeZ_mm: 1; EIA_Code: E192; U/M: EA; AEC Category: Q200
signal-integrity model Resistor
simulation model Resistor
footprint 0603
footprint 0603M
footprint 0603L
footprint 0603_HV
footprint 0603S
pins: 1, 2

## RT0603DRE07196KL
designator R?  ValueDisplayed: 196k  (hidden comment: RT0603DRE07196KL)
RES, 196 k, 0.5%, 0.1 W, 0603; Manufacturer: Yageo America; CompType: Resistor; Value: 196k; Res_ohm: 196000; Tolerance_%: 0.5; Power_W: 0.1; Value2: 0.1W; VDC_V: 75; TempCo: 50 ppm/C; SizeArea_mm2: 1.28; SizeX_mm: 1.6; SizeY_mm: 0.8; SizeZ_mm: 1; EIA_Code: E192; U/M: EA; AEC Category: Q200
signal-integrity model Resistor
simulation model Resistor
footprint 0603
footprint 0603M
footprint 0603L
footprint 0603_HV
footprint 0603S
pins: 1, 2

## RT0603DRE07196RL
designator R?  ValueDisplayed: 196  (hidden comment: RT0603DRE07196RL)
RES, 196, 0.5%, 0.1 W, 0603; Manufacturer: Yageo America; CompType: Resistor; Value: 196; Value_Code: 196R; Tolerance_%: 0.5; Power_W: 0.1; Value2: 0.1W; VDC_V: 75; TempCo: 50 ppm/C; SizeArea_mm2: 1.28; SizeX_mm: 1.6; SizeY_mm: 0.8; SizeZ_mm: 1; EIA_Code: E192; U/M: EA; AEC Category: Q200
signal-integrity model Resistor
simulation model Resistor
footprint 0603
footprint 0603M
footprint 0603L
footprint 0603_HV
footprint 0603S
pins: 1, 2

## RT0603DRE07198KL
designator R?  ValueDisplayed: 198k  (hidden comment: RT0603DRE07198KL)
RES, 198 k, 0.5%, 0.1 W, 0603; Manufacturer: Yageo America; CompType: Resistor; Value: 198k; Res_ohm: 198000; Tolerance_%: 0.5; Power_W: 0.1; Value2: 0.1W; VDC_V: 75; TempCo: 50 ppm/C; SizeArea_mm2: 1.28; SizeX_mm: 1.6; SizeY_mm: 0.8; SizeZ_mm: 1; EIA_Code: E192; U/M: EA; AEC Category: Q200
signal-integrity model Resistor
simulation model Resistor
footprint 0603
footprint 0603M
footprint 0603L
footprint 0603_HV
footprint 0603S
pins: 1, 2

## RT0603DRE07198RL
designator R?  ValueDisplayed: 198  (hidden comment: RT0603DRE07198RL)
RES, 198, 0.5%, 0.1 W, 0603; Manufacturer: Yageo America; CompType: Resistor; Value: 198; Value_Code: 198R; Tolerance_%: 0.5; Power_W: 0.1; Value2: 0.1W; VDC_V: 75; TempCo: 50 ppm/C; SizeArea_mm2: 1.28; SizeX_mm: 1.6; SizeY_mm: 0.8; SizeZ_mm: 1; EIA_Code: E192; U/M: EA; AEC Category: Q200
signal-integrity model Resistor
simulation model Resistor
footprint 0603
footprint 0603M
footprint 0603L
footprint 0603_HV
footprint 0603S
pins: 1, 2

## RT0603DRE07200KL
designator R?  ValueDisplayed: 200k  (hidden comment: RT0603DRE07200KL)
RES, 200 k, 0.5%, 0.1 W, 0603; Manufacturer: Yageo America; CompType: Resistor; Value: 200k; Res_ohm: 200000; Tolerance_%: 0.5; Power_W: 0.1; Value2: 0.1W; VDC_V: 75; TempCo: 50 ppm/C; SizeArea_mm2: 1.28; SizeX_mm: 1.6; SizeY_mm: 0.8; SizeZ_mm: 1; EIA_Code: E192; U/M: EA; AEC Category: Q200; Green_Lifecycle: Active; Green_REACh: Passed
signal-integrity model Resistor
simulation model Resistor
footprint 0603
footprint 0603M
footprint 0603L
footprint 0603_HV
footprint 0603S
pins: 1, 2

## RT0603DRE07200RL
designator R?  ValueDisplayed: 200  (hidden comment: RT0603DRE07200RL)
RES, 200, 0.5%, 0.1 W, 0603; Manufacturer: Yageo America; CompType: Resistor; Value: 200; Value_Code: 200R; Tolerance_%: 0.5; Power_W: 0.1; Value2: 0.1W; VDC_V: 75; TempCo: 50 ppm/C; SizeArea_mm2: 1.28; SizeX_mm: 1.6; SizeY_mm: 0.8; SizeZ_mm: 1; EIA_Code: E192; U/M: EA; AEC Category: Q200
signal-integrity model Resistor
simulation model Resistor
footprint 0603
footprint 0603M
footprint 0603L
footprint 0603_HV
footprint 0603S
pins: 1, 2

## RT0603DRE07203KL
designator R?  ValueDisplayed: 203k  (hidden comment: RT0603DRE07203KL)
RES, 203 k, 0.5%, 0.1 W, 0603; Manufacturer: Yageo America; CompType: Resistor; Value: 203k; Res_ohm: 203000; Tolerance_%: 0.5; Power_W: 0.1; Value2: 0.1W; VDC_V: 75; TempCo: 50 ppm/C; SizeArea_mm2: 1.28; SizeX_mm: 1.6; SizeY_mm: 0.8; SizeZ_mm: 1; EIA_Code: E192; U/M: EA; AEC Category: Q200
signal-integrity model Resistor
simulation model Resistor
footprint 0603
footprint 0603M
footprint 0603L
footprint 0603_HV
footprint 0603S
pins: 1, 2

## RT0603DRE07203RL
designator R?  ValueDisplayed: 203  (hidden comment: RT0603DRE07203RL)
RES, 203, 0.5%, 0.1 W, 0603; Manufacturer: Yageo America; CompType: Resistor; Value: 203; Value_Code: 203R; Tolerance_%: 0.5; Power_W: 0.1; Value2: 0.1W; VDC_V: 75; TempCo: 50 ppm/C; SizeArea_mm2: 1.28; SizeX_mm: 1.6; SizeY_mm: 0.8; SizeZ_mm: 1; EIA_Code: E192; U/M: EA; AEC Category: Q200
signal-integrity model Resistor
simulation model Resistor
footprint 0603
footprint 0603M
footprint 0603L
footprint 0603_HV
footprint 0603S
pins: 1, 2

## RT0603DRE07205KL
designator R?  ValueDisplayed: 205k  (hidden comment: RT0603DRE07205KL)
RES, 205 k, 0.5%, 0.1 W, 0603; Manufacturer: Yageo America; CompType: Resistor; Value: 205k; Res_ohm: 205000; Tolerance_%: 0.5; Power_W: 0.1; Value2: 0.1W; VDC_V: 75; TempCo: 50 ppm/C; SizeArea_mm2: 1.28; SizeX_mm: 1.6; SizeY_mm: 0.8; SizeZ_mm: 1; EIA_Code: E192; U/M: EA; AEC Category: Q200
signal-integrity model Resistor
simulation model Resistor
footprint 0603
footprint 0603M
footprint 0603L
footprint 0603_HV
footprint 0603S
pins: 1, 2

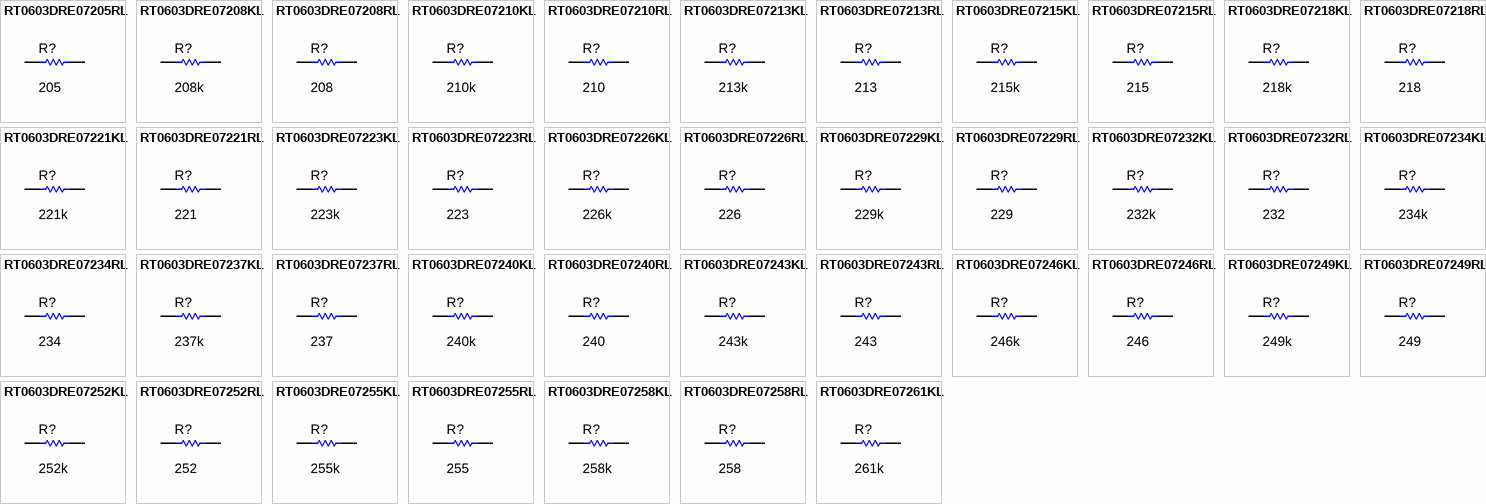
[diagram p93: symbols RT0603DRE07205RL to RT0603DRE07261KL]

## RT0603DRE07205RL
designator R?  ValueDisplayed: 205  (hidden comment: RT0603DRE07205RL)
RES, 205, 0.5%, 0.1 W, 0603; Manufacturer: Yageo America; CompType: Resistor; Value: 205; Value_Code: 205R; Tolerance_%: 0.5; Power_W: 0.1; Value2: 0.1W; VDC_V: 75; TempCo: 50 ppm/C; SizeArea_mm2: 1.28; SizeX_mm: 1.6; SizeY_mm: 0.8; SizeZ_mm: 1; EIA_Code: E192; U/M: EA; AEC Category: Q200
signal-integrity model Resistor
simulation model Resistor
footprint 0603
footprint 0603M
footprint 0603L
footprint 0603_HV
footprint 0603S
pins: 1, 2

## RT0603DRE07208KL
designator R?  ValueDisplayed: 208k  (hidden comment: RT0603DRE07208KL)
RES, 208 k, 0.5%, 0.1 W, 0603; Manufacturer: Yageo America; CompType: Resistor; Value: 208k; Res_ohm: 208000; Tolerance_%: 0.5; Power_W: 0.1; Value2: 0.1W; VDC_V: 75; TempCo: 50 ppm/C; SizeArea_mm2: 1.28; SizeX_mm: 1.6; SizeY_mm: 0.8; SizeZ_mm: 1; EIA_Code: E192; U/M: EA; AEC Category: Q200
signal-integrity model Resistor
simulation model Resistor
footprint 0603
footprint 0603M
footprint 0603L
footprint 0603_HV
footprint 0603S
pins: 1, 2

## RT0603DRE07208RL
designator R?  ValueDisplayed: 208  (hidden comment: RT0603DRE07208RL)
RES, 208, 0.5%, 0.1 W, 0603; Manufacturer: Yageo America; CompType: Resistor; Value: 208; Value_Code: 208R; Tolerance_%: 0.5; Power_W: 0.1; Value2: 0.1W; VDC_V: 75; TempCo: 50 ppm/C; SizeArea_mm2: 1.28; SizeX_mm: 1.6; SizeY_mm: 0.8; SizeZ_mm: 1; EIA_Code: E192; U/M: EA; AEC Category: Q200
signal-integrity model Resistor
simulation model Resistor
footprint 0603
footprint 0603M
footprint 0603L
footprint 0603_HV
footprint 0603S
pins: 1, 2

## RT0603DRE07210KL
designator R?  ValueDisplayed: 210k  (hidden comment: RT0603DRE07210KL)
RES, 210 k, 0.5%, 0.1 W, 0603; Manufacturer: Yageo America; CompType: Resistor; Value: 210k; Res_ohm: 210000; Tolerance_%: 0.5; Power_W: 0.1; Value2: 0.1W; VDC_V: 75; TempCo: 50 ppm/C; SizeArea_mm2: 1.28; SizeX_mm: 1.6; SizeY_mm: 0.8; SizeZ_mm: 1; EIA_Code: E192; U/M: EA; AEC Category: Q200
signal-integrity model Resistor
simulation model Resistor
footprint 0603
footprint 0603M
footprint 0603L
footprint 0603_HV
footprint 0603S
pins: 1, 2

## RT0603DRE07210RL
designator R?  ValueDisplayed: 210  (hidden comment: RT0603DRE07210RL)
RES, 210, 0.5%, 0.1 W, 0603; Manufacturer: Yageo America; CompType: Resistor; Value: 210; Value_Code: 210R; Tolerance_%: 0.5; Power_W: 0.1; Value2: 0.1W; VDC_V: 75; TempCo: 50 ppm/C; SizeArea_mm2: 1.28; SizeX_mm: 1.6; SizeY_mm: 0.8; SizeZ_mm: 1; EIA_Code: E192; U/M: EA; AEC Category: Q200
signal-integrity model Resistor
simulation model Resistor
footprint 0603
footprint 0603M
footprint 0603L
footprint 0603_HV
footprint 0603S
pins: 1, 2

## RT0603DRE07213KL
designator R?  ValueDisplayed: 213k  (hidden comment: RT0603DRE07213KL)
RES, 213 k, 0.5%, 0.1 W, 0603; Manufacturer: Yageo America; CompType: Resistor; Value: 213k; Res_ohm: 213000; Tolerance_%: 0.5; Power_W: 0.1; Value2: 0.1W; VDC_V: 75; TempCo: 50 ppm/C; SizeArea_mm2: 1.28; SizeX_mm: 1.6; SizeY_mm: 0.8; SizeZ_mm: 1; EIA_Code: E192; U/M: EA; AEC Category: Q200
signal-integrity model Resistor
simulation model Resistor
footprint 0603
footprint 0603M
footprint 0603L
footprint 0603_HV
footprint 0603S
pins: 1, 2

## RT0603DRE07213RL
designator R?  ValueDisplayed: 213  (hidden comment: RT0603DRE07213RL)
RES, 213, 0.5%, 0.1 W, 0603; Manufacturer: Yageo America; CompType: Resistor; Value: 213; Value_Code: 213R; Tolerance_%: 0.5; Power_W: 0.1; Value2: 0.1W; VDC_V: 75; TempCo: 50 ppm/C; SizeArea_mm2: 1.28; SizeX_mm: 1.6; SizeY_mm: 0.8; SizeZ_mm: 1; EIA_Code: E192; U/M: EA; AEC Category: Q200
signal-integrity model Resistor
simulation model Resistor
footprint 0603
footprint 0603M
footprint 0603L
footprint 0603_HV
footprint 0603S
pins: 1, 2

## RT0603DRE07215KL
designator R?  ValueDisplayed: 215k  (hidden comment: RT0603DRE07215KL)
RES, 215 k, 0.5%, 0.1 W, 0603; Manufacturer: Yageo America; CompType: Resistor; Value: 215k; Res_ohm: 215000; Tolerance_%: 0.5; Power_W: 0.1; Value2: 0.1W; VDC_V: 75; TempCo: 50 ppm/C; SizeArea_mm2: 1.28; SizeX_mm: 1.6; SizeY_mm: 0.8; SizeZ_mm: 1; EIA_Code: E192; U/M: EA; AEC Category: Q200
signal-integrity model Resistor
simulation model Resistor
footprint 0603
footprint 0603M
footprint 0603L
footprint 0603_HV
footprint 0603S
pins: 1, 2

## RT0603DRE07215RL
designator R?  ValueDisplayed: 215  (hidden comment: RT0603DRE07215RL)
RES, 215, 0.5%, 0.1 W, 0603; Manufacturer: Yageo America; CompType: Resistor; Value: 215; Value_Code: 215R; Tolerance_%: 0.5; Power_W: 0.1; Value2: 0.1W; VDC_V: 75; TempCo: 50 ppm/C; SizeArea_mm2: 1.28; SizeX_mm: 1.6; SizeY_mm: 0.8; SizeZ_mm: 1; EIA_Code: E192; U/M: EA; AEC Category: Q200
signal-integrity model Resistor
simulation model Resistor
footprint 0603
footprint 0603M
footprint 0603L
footprint 0603_HV
footprint 0603S
pins: 1, 2

## RT0603DRE07218KL
designator R?  ValueDisplayed: 218k  (hidden comment: RT0603DRE07218KL)
RES, 218 k, 0.5%, 0.1 W, 0603; Manufacturer: Yageo America; CompType: Resistor; Value: 218k; Res_ohm: 218000; Tolerance_%: 0.5; Power_W: 0.1; Value2: 0.1W; VDC_V: 75; TempCo: 50 ppm/C; SizeArea_mm2: 1.28; SizeX_mm: 1.6; SizeY_mm: 0.8; SizeZ_mm: 1; EIA_Code: E192; U/M: EA; AEC Category: Q200
signal-integrity model Resistor
simulation model Resistor
footprint 0603
footprint 0603M
footprint 0603L
footprint 0603_HV
footprint 0603S
pins: 1, 2

## RT0603DRE07218RL
designator R?  ValueDisplayed: 218  (hidden comment: RT0603DRE07218RL)
RES, 218, 0.5%, 0.1 W, 0603; Manufacturer: Yageo America; CompType: Resistor; Value: 218; Value_Code: 218R; Tolerance_%: 0.5; Power_W: 0.1; Value2: 0.1W; VDC_V: 75; TempCo: 50 ppm/C; SizeArea_mm2: 1.28; SizeX_mm: 1.6; SizeY_mm: 0.8; SizeZ_mm: 1; EIA_Code: E192; U/M: EA; AEC Category: Q200
signal-integrity model Resistor
simulation model Resistor
footprint 0603
footprint 0603M
footprint 0603L
footprint 0603_HV
footprint 0603S
pins: 1, 2

## RT0603DRE07221KL
designator R?  ValueDisplayed: 221k  (hidden comment: RT0603DRE07221KL)
RES, 221 k, 0.5%, 0.1 W, 0603; Manufacturer: Yageo America; CompType: Resistor; Value: 221k; Res_ohm: 221000; Tolerance_%: 0.5; Power_W: 0.1; Value2: 0.1W; VDC_V: 75; TempCo: 50 ppm/C; SizeArea_mm2: 1.28; SizeX_mm: 1.6; SizeY_mm: 0.8; SizeZ_mm: 1; EIA_Code: E192; U/M: EA; AEC Category: Q200
signal-integrity model Resistor
simulation model Resistor
footprint 0603
footprint 0603M
footprint 0603L
footprint 0603_HV
footprint 0603S
pins: 1, 2

## RT0603DRE07221RL
designator R?  ValueDisplayed: 221  (hidden comment: RT0603DRE07221RL)
RES, 221, 0.5%, 0.1 W, 0603; Manufacturer: Yageo America; CompType: Resistor; Value: 221; Value_Code: 221R; Tolerance_%: 0.5; Power_W: 0.1; Value2: 0.1W; VDC_V: 75; TempCo: 50 ppm/C; SizeArea_mm2: 1.28; SizeX_mm: 1.6; SizeY_mm: 0.8; SizeZ_mm: 1; EIA_Code: E192; U/M: EA; AEC Category: Q200
signal-integrity model Resistor
simulation model Resistor
footprint 0603
footprint 0603M
footprint 0603L
footprint 0603_HV
footprint 0603S
pins: 1, 2

## RT0603DRE07223KL
designator R?  ValueDisplayed: 223k  (hidden comment: RT0603DRE07223KL)
RES, 223 k, 0.5%, 0.1 W, 0603; Manufacturer: Yageo America; CompType: Resistor; Value: 223k; Res_ohm: 223000; Tolerance_%: 0.5; Power_W: 0.1; Value2: 0.1W; VDC_V: 75; TempCo: 50 ppm/C; SizeArea_mm2: 1.28; SizeX_mm: 1.6; SizeY_mm: 0.8; SizeZ_mm: 1; EIA_Code: E192; U/M: EA; AEC Category: Q200
signal-integrity model Resistor
simulation model Resistor
footprint 0603
footprint 0603M
footprint 0603L
footprint 0603_HV
footprint 0603S
pins: 1, 2

## RT0603DRE07223RL
designator R?  ValueDisplayed: 223  (hidden comment: RT0603DRE07223RL)
RES, 223, 0.5%, 0.1 W, 0603; Manufacturer: Yageo America; CompType: Resistor; Value: 223; Value_Code: 223R; Tolerance_%: 0.5; Power_W: 0.1; Value2: 0.1W; VDC_V: 75; TempCo: 50 ppm/C; SizeArea_mm2: 1.28; SizeX_mm: 1.6; SizeY_mm: 0.8; SizeZ_mm: 1; EIA_Code: E192; U/M: EA; AEC Category: Q200
signal-integrity model Resistor
simulation model Resistor
footprint 0603
footprint 0603M
footprint 0603L
footprint 0603_HV
footprint 0603S
pins: 1, 2

## RT0603DRE07226KL
designator R?  ValueDisplayed: 226k  (hidden comment: RT0603DRE07226KL)
RES, 226 k, 0.5%, 0.1 W, 0603; Manufacturer: Yageo America; CompType: Resistor; Value: 226k; Res_ohm: 226000; Tolerance_%: 0.5; Power_W: 0.1; Value2: 0.1W; VDC_V: 75; TempCo: 50 ppm/C; SizeArea_mm2: 1.28; SizeX_mm: 1.6; SizeY_mm: 0.8; SizeZ_mm: 1; EIA_Code: E192; U/M: EA; AEC Category: Q200
signal-integrity model Resistor
simulation model Resistor
footprint 0603
footprint 0603M
footprint 0603L
footprint 0603_HV
footprint 0603S
pins: 1, 2

## RT0603DRE07226RL
designator R?  ValueDisplayed: 226  (hidden comment: RT0603DRE07226RL)
RES, 226, 0.5%, 0.1 W, 0603; Manufacturer: Yageo America; CompType: Resistor; Value: 226; Value_Code: 226R; Tolerance_%: 0.5; Power_W: 0.1; Value2: 0.1W; VDC_V: 75; TempCo: 50 ppm/C; SizeArea_mm2: 1.28; SizeX_mm: 1.6; SizeY_mm: 0.8; SizeZ_mm: 1; EIA_Code: E192; U/M: EA; AEC Category: Q200
signal-integrity model Resistor
simulation model Resistor
footprint 0603
footprint 0603M
footprint 0603L
footprint 0603_HV
footprint 0603S
pins: 1, 2

## RT0603DRE07229KL
designator R?  ValueDisplayed: 229k  (hidden comment: RT0603DRE07229KL)
RES, 229 k, 0.5%, 0.1 W, 0603; Manufacturer: Yageo America; CompType: Resistor; Value: 229k; Res_ohm: 229000; Tolerance_%: 0.5; Power_W: 0.1; Value2: 0.1W; VDC_V: 75; TempCo: 50 ppm/C; SizeArea_mm2: 1.28; SizeX_mm: 1.6; SizeY_mm: 0.8; SizeZ_mm: 1; EIA_Code: E192; U/M: EA; AEC Category: Q200
signal-integrity model Resistor
simulation model Resistor
footprint 0603
footprint 0603M
footprint 0603L
footprint 0603_HV
footprint 0603S
pins: 1, 2

## RT0603DRE07229RL
designator R?  ValueDisplayed: 229  (hidden comment: RT0603DRE07229RL)
RES, 229, 0.5%, 0.1 W, 0603; Manufacturer: Yageo America; CompType: Resistor; Value: 229; Value_Code: 229R; Tolerance_%: 0.5; Power_W: 0.1; Value2: 0.1W; VDC_V: 75; TempCo: 50 ppm/C; SizeArea_mm2: 1.28; SizeX_mm: 1.6; SizeY_mm: 0.8; SizeZ_mm: 1; EIA_Code: E192; U/M: EA; AEC Category: Q200
signal-integrity model Resistor
simulation model Resistor
footprint 0603
footprint 0603M
footprint 0603L
footprint 0603_HV
footprint 0603S
pins: 1, 2

## RT0603DRE07232KL
designator R?  ValueDisplayed: 232k  (hidden comment: RT0603DRE07232KL)
RES, 232 k, 0.5%, 0.1 W, 0603; Manufacturer: Yageo America; CompType: Resistor; Value: 232k; Res_ohm: 232000; Tolerance_%: 0.5; Power_W: 0.1; Value2: 0.1W; VDC_V: 75; TempCo: 50 ppm/C; SizeArea_mm2: 1.28; SizeX_mm: 1.6; SizeY_mm: 0.8; SizeZ_mm: 1; EIA_Code: E192; U/M: EA; AEC Category: Q200
signal-integrity model Resistor
simulation model Resistor
footprint 0603
footprint 0603M
footprint 0603L
footprint 0603_HV
footprint 0603S
pins: 1, 2

## RT0603DRE07232RL
designator R?  ValueDisplayed: 232  (hidden comment: RT0603DRE07232RL)
RES, 232, 0.5%, 0.1 W, 0603; Manufacturer: Yageo America; CompType: Resistor; Value: 232; Value_Code: 232R; Tolerance_%: 0.5; Power_W: 0.1; Value2: 0.1W; VDC_V: 75; TempCo: 50 ppm/C; SizeArea_mm2: 1.28; SizeX_mm: 1.6; SizeY_mm: 0.8; SizeZ_mm: 1; EIA_Code: E192; U/M: EA; AEC Category: Q200
signal-integrity model Resistor
simulation model Resistor
footprint 0603
footprint 0603M
footprint 0603L
footprint 0603_HV
footprint 0603S
pins: 1, 2

## RT0603DRE07234KL
designator R?  ValueDisplayed: 234k  (hidden comment: RT0603DRE07234KL)
RES, 234 k, 0.5%, 0.1 W, 0603; Manufacturer: Yageo America; CompType: Resistor; Value: 234k; Res_ohm: 234000; Tolerance_%: 0.5; Power_W: 0.1; Value2: 0.1W; VDC_V: 75; TempCo: 50 ppm/C; SizeArea_mm2: 1.28; SizeX_mm: 1.6; SizeY_mm: 0.8; SizeZ_mm: 1; EIA_Code: E192; U/M: EA; AEC Category: Q200
signal-integrity model Resistor
simulation model Resistor
footprint 0603
footprint 0603M
footprint 0603L
footprint 0603_HV
footprint 0603S
pins: 1, 2

## RT0603DRE07234RL
designator R?  ValueDisplayed: 234  (hidden comment: RT0603DRE07234RL)
RES, 234, 0.5%, 0.1 W, 0603; Manufacturer: Yageo America; CompType: Resistor; Value: 234; Value_Code: 234R; Tolerance_%: 0.5; Power_W: 0.1; Value2: 0.1W; VDC_V: 75; TempCo: 50 ppm/C; SizeArea_mm2: 1.28; SizeX_mm: 1.6; SizeY_mm: 0.8; SizeZ_mm: 1; EIA_Code: E192; U/M: EA; AEC Category: Q200
signal-integrity model Resistor
simulation model Resistor
footprint 0603
footprint 0603M
footprint 0603L
footprint 0603_HV
footprint 0603S
pins: 1, 2

## RT0603DRE07237KL
designator R?  ValueDisplayed: 237k  (hidden comment: RT0603DRE07237KL)
RES, 237 k, 0.5%, 0.1 W, 0603; Manufacturer: Yageo America; CompType: Resistor; Value: 237k; Res_ohm: 237000; Tolerance_%: 0.5; Power_W: 0.1; Value2: 0.1W; VDC_V: 75; TempCo: 50 ppm/C; SizeArea_mm2: 1.28; SizeX_mm: 1.6; SizeY_mm: 0.8; SizeZ_mm: 1; EIA_Code: E192; U/M: EA; AEC Category: Q200
signal-integrity model Resistor
simulation model Resistor
footprint 0603
footprint 0603M
footprint 0603L
footprint 0603_HV
footprint 0603S
pins: 1, 2

## RT0603DRE07237RL
designator R?  ValueDisplayed: 237  (hidden comment: RT0603DRE07237RL)
RES, 237, 0.5%, 0.1 W, 0603; Manufacturer: Yageo America; CompType: Resistor; Value: 237; Value_Code: 237R; Tolerance_%: 0.5; Power_W: 0.1; Value2: 0.1W; VDC_V: 75; TempCo: 50 ppm/C; SizeArea_mm2: 1.28; SizeX_mm: 1.6; SizeY_mm: 0.8; SizeZ_mm: 1; EIA_Code: E192; U/M: EA; AEC Category: Q200
signal-integrity model Resistor
simulation model Resistor
footprint 0603
footprint 0603M
footprint 0603L
footprint 0603_HV
footprint 0603S
pins: 1, 2

## RT0603DRE07240KL
designator R?  ValueDisplayed: 240k  (hidden comment: RT0603DRE07240KL)
RES, 240 k, 0.5%, 0.1 W, 0603; Manufacturer: Yageo America; CompType: Resistor; Value: 240k; Res_ohm: 240000; Tolerance_%: 0.5; Power_W: 0.1; Value2: 0.1W; VDC_V: 75; TempCo: 50 ppm/C; SizeArea_mm2: 1.28; SizeX_mm: 1.6; SizeY_mm: 0.8; SizeZ_mm: 1; EIA_Code: E192; U/M: EA; AEC Category: Q200
signal-integrity model Resistor
simulation model Resistor
footprint 0603
footprint 0603M
footprint 0603L
footprint 0603_HV
footprint 0603S
pins: 1, 2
